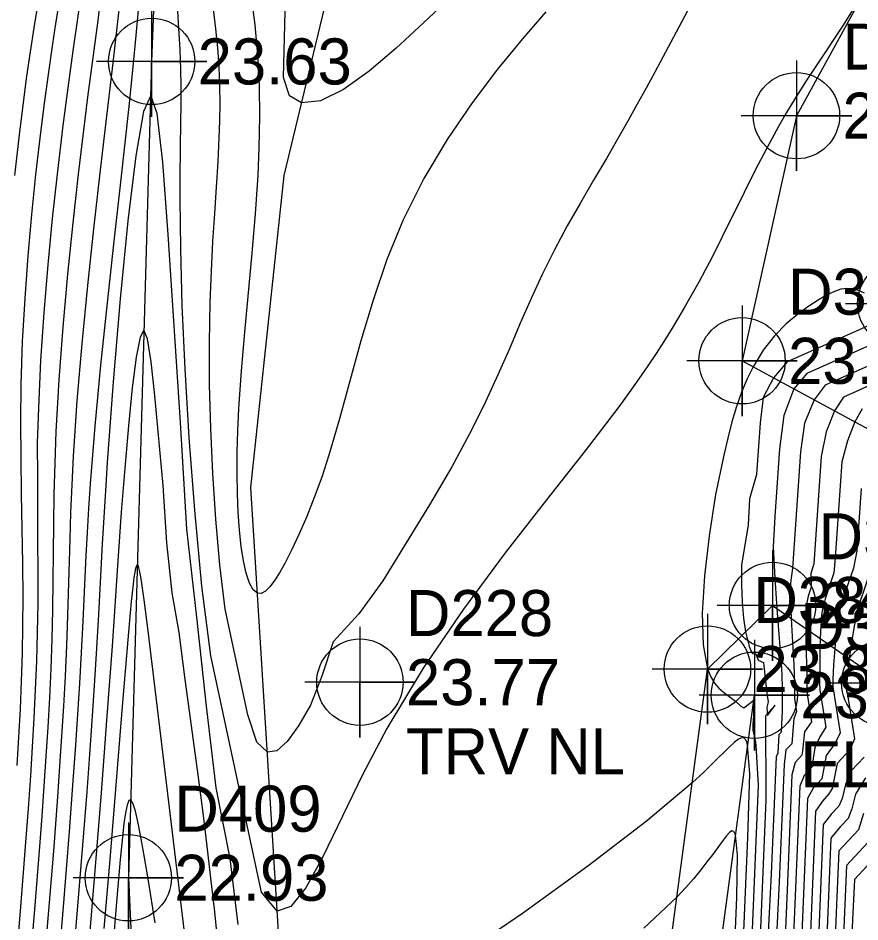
# Model space of a CAD drawing. Extents: x 2356077 to 2359823, y 225951 to 227822.
# Drawn here: x 2356540.32 to 2356586.03, y 227226.48 to 227275.54 of the extents above; entities that cross this region are included whole.
import ezdxf

# ---------------------------------------------------------------- set-up
doc = ezdxf.new("R2010")
doc.units = 0
for name, color, linetype in [('DTM Contours Major', 7, 'Continuous'), ('DTM Contours Minor', 7, 'Continuous'), ('Exist DTM Breakline', 7, 'Continuous'), ('Exist DTM Breakline Cogo Elevation', 7, 'Continuous'), ('Exist DTM Breakline Cogo Number', 7, 'Continuous'), ('Exist DTM Breakline Cogo Point CELL', 7, 'Continuous'), ('Exist DTM Drainline', 7, 'Continuous'), ('Exist DTM Drainline Cogo Comment', 7, 'Continuous'), ('Exist DTM Drainline Cogo Elevation', 7, 'Continuous'), ('Exist DTM Drainline Cogo Number', 7, 'Continuous'), ('Exist DTM Drainline Cogo Point CELL', 7, 'Continuous'), ('Exist DTM Regular Point CELL', 7, 'Continuous'), ('Exist DTM Regular Point Cogo Comment', 7, 'Continuous'), ('Exist DTM Regular Point Cogo Elevation', 7, 'Continuous'), ('Exist DTM Regular Point Cogo Number', 7, 'Continuous'), ('PH Exist DTM Breakline', 7, 'Continuous')]:
    doc.layers.add(name, color=color, linetype=linetype)

msp = doc.modelspace()

# ---------------------------------------------------------------- linework, layer by layer
at = {"layer": 'DTM Contours Major'}
for points in [[(2356545.863, 227276.626), (2356545.708, 227275.192), (2356545.466, 227273.116), (2356545.041, 227269.592), (2356544.734, 227266.981), (2356544.408, 227264.091), (2356544.083, 227261.023), (2356543.779, 227257.879), (2356543.515, 227254.76), (2356543.313, 227251.769), (2356543.232, 227250.207), (2356543.171, 227248.705), (2356543.123, 227247.255), (2356543.004, 227243.122), (2356542.942, 227241.467), (2356542.868, 227239.827), (2356542.781, 227238.196), (2356542.684, 227236.566), (2356542.577, 227234.93), (2356542.46, 227233.279), (2356542.236, 227230.325), (2356541.852, 227225.609)], [(2356576.984, 227276.512), (2356576.192, 227275.047), (2356574.885, 227272.596), (2356574.417, 227271.731), (2356573.94, 227270.86), (2356573.45, 227269.98), (2356572.942, 227269.09), (2356572.263, 227267.925), (2356571.562, 227266.735), (2356570.85, 227265.514), (2356570.141, 227264.256), (2356569.445, 227262.958), (2356568.774, 227261.614), (2356568.176, 227260.316), (2356567.59, 227258.976), (2356566.995, 227257.593), (2356566.372, 227256.171), (2356565.701, 227254.71), (2356564.961, 227253.211), (2356563.864, 227251.188), (2356562.661, 227249.128), (2356561.4, 227247.055), (2356560.128, 227244.994), (2356558.83, 227243.195), (2356557.433, 227241.687), (2356556.839, 227239.877), (2356556.205, 227238.24), (2356555.537, 227237.12), (2356554.927, 227236.272), (2356554.369, 227235.772), (2356553.855, 227235.694), (2356553.279, 227236.237), (2356552.789, 227237.726), (2356551.559, 227243.463), (2356551.275, 227245.855), (2356551.051, 227248.346), (2356550.886, 227250.827), (2356550.777, 227253.27), (2356550.72, 227255.649), (2356550.713, 227257.937), (2356550.752, 227260.107), (2356550.817, 227261.804), (2356550.903, 227263.409), (2356550.998, 227264.926), (2356551.093, 227266.365), (2356551.179, 227267.73), (2356551.244, 227269.03), (2356551.275, 227269.959), (2356551.286, 227270.866), (2356551.273, 227271.885), (2356551.232, 227272.9), (2356551.162, 227273.92), (2356551.062, 227274.956), (2356550.93, 227276.017)], [(2356587.908, 227259.469), (2356582.081, 227256.874), (2356581.332, 227256.017), (2356580.772, 227254.938), (2356580.613, 227253.573), (2356580.418, 227250.761), (2356580.043, 227249.442), (2356579.968, 227248.029), (2356579.601, 227245.844), (2356579.595, 227244.795), (2356579.64, 227243.834), (2356579.716, 227242.974), (2356579.825, 227242.235), (2356579.886, 227241.946), (2356579.953, 227241.681), (2356580.024, 227241.437), (2356580.098, 227241.21), (2356580.206, 227241.054), (2356580.382, 227241.027), (2356580.508, 227240.682), (2356580.788, 227240.568), (2356580.944, 227239.211), (2356580.999, 227238.773), (2356581.054, 227238.425), (2356580.979, 227238.136), (2356581.018, 227237.678), (2356581.433, 227238.239), (2356580.903, 227237.669), (2356580.928, 227233.104), (2356580.177, 227215.223)], [(2356586.099, 227250.001), (2356585.866, 227246.627), (2356585.676, 227245.691), (2356585.056, 227243.861), (2356584.838, 227242.954), (2356584.738, 227242.108), (2356584.663, 227241.324), (2356584.628, 227240.869), (2356584.602, 227240.438), (2356584.567, 227239.63), (2356584.555, 227239.247), (2356584.881, 227237.205), (2356584.956, 227236.739), (2356584.678, 227236.184), (2356584.19, 227235.518), (2356583.963, 227234.24), (2356583.498, 227233.741), (2356583.192, 227233.181), (2356582.829, 227224.549)], [(2356547.761, 227226.437), (2356547.379, 227228.812), (2356547.185, 227229.973), (2356547.005, 227230.989), (2356546.84, 227231.836), (2356546.688, 227232.489), (2356546.551, 227232.923), (2356546.427, 227233.115), (2356546.327, 227233.068), (2356546.236, 227232.826), (2356546.15, 227232.405), (2356546.067, 227231.819), (2356545.984, 227231.084), (2356545.869, 227229.879), (2356545.705, 227227.988), (2356545.434, 227224.703)], [(2356586.466, 227230.801), (2356585.3, 227229.549), (2356585.103, 227224.873)]]:
    msp.add_lwpolyline(points, dxfattribs=at)
at = {"layer": 'DTM Contours Minor'}
for points in [[(2356563.774, 227276.657), (2356562.341, 227275.276), (2356560.853, 227273.898), (2356559.379, 227272.65), (2356557.987, 227271.656), (2356556.744, 227271.045), (2356555.717, 227270.941), (2356555.058, 227271.316), (2356554.728, 227272.312), (2356554.891, 227278.786)], [(2356543.852, 227277.663), (2356543.291, 227273.755), (2356543.014, 227271.748), (2356542.749, 227269.703), (2356542.433, 227267.059), (2356542.174, 227264.669), (2356541.931, 227262.153), (2356541.716, 227259.564), (2356541.544, 227256.956), (2356541.428, 227254.385), (2356541.357, 227252.459), (2356541.365, 227250.684), (2356541.366, 227248.9), (2356541.392, 227243.756), (2356541.312, 227240.643), (2356541.253, 227239.098), (2356541.179, 227237.55), (2356541.09, 227235.992), (2356540.99, 227234.415), (2356540.865, 227232.636), (2356540.729, 227230.819), (2356540.429, 227227.059), (2356539.894, 227220.582)], [(2356544.857, 227277.102), (2356544.642, 227275.415), (2356544.094, 227271.249), (2356543.869, 227269.459), (2356543.583, 227267.062), (2356543.29, 227264.428), (2356543.006, 227261.637), (2356542.748, 227258.767), (2356542.532, 227255.897), (2356542.374, 227253.106), (2356542.31, 227251.374), (2356542.269, 227249.701), (2356542.244, 227248.079), (2356542.194, 227243.44), (2356542.146, 227241.829), (2356542.089, 227240.234), (2356542.017, 227238.647), (2356541.932, 227237.059), (2356541.834, 227235.463), (2356541.726, 227233.85), (2356541.609, 227232.229), (2356541.483, 227230.577), (2356541.208, 227227.152), (2356540.688, 227220.881)], [(2356546.877, 227276.368), (2356546.721, 227274.595), (2356546.556, 227272.898), (2356546.33, 227270.731), (2356545.875, 227266.634), (2356545.516, 227263.429), (2356545.149, 227260.081), (2356544.799, 227256.699), (2356544.486, 227253.391), (2356544.235, 227250.266), (2356544.145, 227248.919), (2356544.069, 227247.625), (2356544.003, 227246.376), (2356543.833, 227242.809), (2356543.746, 227241.111), (2356543.65, 227239.429), (2356543.546, 227237.754), (2356543.435, 227236.08), (2356543.317, 227234.4), (2356543.092, 227231.396), (2356542.763, 227227.301), (2356542.028, 227218.472)], [(2356568.977, 227275.87), (2356567.703, 227274.419), (2356566.349, 227272.768), (2356564.97, 227270.937), (2356563.621, 227268.95), (2356562.357, 227266.827), (2356561.232, 227264.591), (2356560.346, 227262.427), (2356559.592, 227260.225), (2356558.937, 227258.022), (2356557.776, 227253.779), (2356557.199, 227251.819), (2356556.806, 227250.63), (2356556.4, 227249.516), (2356555.99, 227248.483), (2356555.581, 227247.538), (2356555.18, 227246.687), (2356554.795, 227245.938), (2356554.512, 227245.435), (2356554.244, 227245.009), (2356553.989, 227244.672), (2356553.75, 227244.436), (2356553.527, 227244.314), (2356553.32, 227244.318), (2356553.091, 227244.504), (2356552.888, 227244.876), (2356552.711, 227245.408), (2356552.561, 227246.08), (2356552.437, 227246.867), (2356552.341, 227247.747), (2356552.271, 227248.709), (2356552.228, 227249.734), (2356552.21, 227250.817), (2356552.219, 227251.952), (2356552.252, 227253.131), (2356552.308, 227254.348), (2356552.447, 227256.394), (2356552.627, 227258.499), (2356553.029, 227262.783), (2356553.21, 227264.913), (2356553.351, 227267.003), (2356553.399, 227268.004), (2356553.418, 227268.499), (2356553.448, 227270.194), (2356553.423, 227271.865), (2356553.339, 227273.52), (2356553.19, 227275.168), (2356552.972, 227276.817)], [(2356541.383, 227276.323), (2356541.171, 227275.015), (2356540.971, 227273.703), (2356540.782, 227272.379), (2356540.557, 227270.674), (2356540.378, 227269.209), (2356540.133, 227266.994)], [(2356542.481, 227276.017), (2356542.302, 227274.891), (2356542.13, 227273.757), (2356541.963, 227272.604), (2356541.751, 227271.041), (2356541.553, 227269.476), (2356541.271, 227267.041), (2356541.05, 227264.885), (2356540.849, 227262.635), (2356540.679, 227260.321), (2356540.55, 227257.977), (2356540.472, 227255.634), (2356540.449, 227253.637), (2356540.46, 227251.666), (2356540.49, 227249.724), (2356540.56, 227245.934), (2356540.575, 227244.09), (2356540.565, 227242.562), (2356540.536, 227241.05), (2356540.489, 227239.545), (2356540.424, 227238.038), (2356540.345, 227236.518), (2356540.252, 227234.978)], [(2356585.816, 227276.254), (2356585.113, 227275.158), (2356583.759, 227273.109), (2356583.116, 227272.128), (2356582.5, 227271.156), (2356582.048, 227270.408), (2356581.61, 227269.651), (2356580.968, 227268.476), (2356580.347, 227267.277), (2356579.741, 227266.068), (2356578.554, 227263.665), (2356577.962, 227262.496), (2356577.624, 227261.851), (2356577.28, 227261.213), (2356576.927, 227260.576), (2356576.561, 227259.936), (2356576.18, 227259.288), (2356575.778, 227258.626), (2356575.383, 227257.993), (2356574.963, 227257.339), (2356574.514, 227256.661), (2356574.03, 227255.954), (2356573.507, 227255.216), (2356572.941, 227254.441), (2356571.111, 227252.054), (2356569.015, 227249.397), (2356566.773, 227246.514), (2356564.501, 227243.453), (2356562.317, 227240.262), (2356560.34, 227236.986), (2356559.018, 227234.458), (2356556.849, 227229.974), (2356555.949, 227228.337), (2356555.138, 227227.315), (2356554.39, 227227.07), (2356553.539, 227228.096), (2356550.791, 227240.917), (2356550.303, 227244.712), (2356549.912, 227248.826), (2356549.61, 227252.776), (2356549.387, 227256.502), (2356549.237, 227259.942), (2356549.15, 227263.034), (2356549.117, 227265.716), (2356549.118, 227266.766), (2356549.137, 227268.622), (2356549.171, 227270.924), (2356549.173, 227271.858), (2356549.16, 227272.753), (2356549.143, 227273.29), (2356549.12, 227273.834), (2356549.056, 227274.975), (2356548.968, 227276.238)], [(2356552.273, 227226.346), (2356551.833, 227229.926), (2356551.08, 227233.753), (2356550.544, 227238.199), (2356550.026, 227243.023), (2356549.486, 227247.808), (2356549.137, 227253.58), (2356548.476, 227263.793), (2356548.176, 227267.71), (2356547.865, 227270.351), (2356547.519, 227271.339), (2356547.131, 227270.467), (2356546.71, 227268.059), (2356546.279, 227264.532), (2356545.863, 227260.304), (2356545.483, 227255.792), (2356545.165, 227251.414), (2356545.065, 227249.873), (2356544.893, 227247.005), (2356544.678, 227243.161), (2356544.553, 227241.032), (2356544.429, 227239.032), (2356544.304, 227237.134), (2356544.177, 227235.312), (2356544.047, 227233.538), (2356543.823, 227230.648), (2356543.533, 227227.119), (2356542.805, 227218.528)], [(2356586.28, 227260.601), (2356585.954, 227260.755), (2356585.635, 227260.849), (2356585.319, 227260.869), (2356584.993, 227260.819), (2356584.643, 227260.699), (2356584.253, 227260.511), (2356583.809, 227260.257), (2356583.26, 227259.907), (2356582.657, 227259.471), (2356582.026, 227258.935), (2356581.393, 227258.289), (2356580.785, 227257.519), (2356580.226, 227256.615), (2356579.902, 227255.952), (2356579.605, 227255.23), (2356579.334, 227254.453), (2356579.083, 227253.624), (2356578.851, 227252.745), (2356578.632, 227251.821), (2356578.196, 227249.673), (2356577.838, 227247.445), (2356577.587, 227245.26), (2356577.47, 227243.244), (2356577.515, 227241.52), (2356577.752, 227240.211), (2356577.927, 227239.785), (2356578.136, 227239.448), (2356578.371, 227239.178), (2356578.622, 227238.957), (2356579.134, 227238.572), (2356579.28, 227238.455), (2356579.565, 227238.201), (2356579.734, 227238.101), (2356580.264, 227238.514), (2356580.249, 227238.219), (2356580.245, 227237.821), (2356580.247, 227237.661), (2356580.239, 227237.454), (2356580.223, 227237.185), (2356580.216, 227236.885), (2356580.289, 227236.58), (2356580.354, 227236.245), (2356580.383, 227236.065), (2356580.51, 227233.908), (2356579.704, 227214.729)], [(2356551.154, 227225.581), (2356550.981, 227227.187), (2356550.793, 227228.859), (2356550.587, 227230.6), (2356550.361, 227232.411), (2356550.058, 227234.731), (2356549.399, 227239.64), (2356549.067, 227242.198), (2356548.691, 227244.337), (2356548.397, 227247.056), (2356548.193, 227250.165), (2356547.747, 227255.045), (2356547.549, 227256.887), (2356547.354, 227258.123), (2356547.155, 227258.599), (2356546.949, 227258.227), (2356546.735, 227257.132), (2356546.519, 227255.475), (2356546.308, 227253.416), (2356546.107, 227251.114), (2356545.922, 227248.73), (2356545.736, 227246.085), (2356545.419, 227241.442), (2356545.128, 227237.406), (2356544.828, 227233.49), (2356544.504, 227229.482), (2356544.135, 227225.107)], [(2356588.484, 227258.635), (2356583.142, 227256.256), (2356582.437, 227255.419), (2356581.894, 227253.967), (2356581.662, 227252.165), (2356581.408, 227248.484), (2356581.319, 227246.848), (2356581.403, 227245.139), (2356581.499, 227243.758), (2356581.519, 227243.502), (2356581.705, 227241.173), (2356581.752, 227240.5), (2356581.787, 227239.851), (2356581.808, 227239.21), (2356581.812, 227238.574), (2356581.801, 227237.914), (2356581.772, 227237.213), (2356581.75, 227236.807), (2356581.798, 227236.817), (2356581.634, 227236.641), (2356581.573, 227235.65), (2356581.478, 227235.438), (2356581.211, 227229.087), (2356581.047, 227225.915)], [(2356588.947, 227257.751), (2356584.137, 227255.608), (2356583.543, 227254.82), (2356583.028, 227253.561), (2356582.797, 227251.989), (2356582.361, 227245.69), (2356582.307, 227245.29), (2356582.268, 227244.863), (2356582.254, 227244.401), (2356582.266, 227243.904), (2356582.305, 227242.957), (2356582.376, 227241.641), (2356582.441, 227240.457), (2356582.463, 227239.89), (2356582.476, 227239.329), (2356582.476, 227238.617), (2356582.589, 227237.911), (2356582.447, 227237.498), (2356582.398, 227237.083), (2356582.325, 227236.157), (2356582.01, 227235.82), (2356581.913, 227235.033), (2356581.646, 227228.666), (2356581.346, 227222.377)], [(2356589.385, 227256.856), (2356585.138, 227254.964), (2356584.648, 227254.222), (2356584.191, 227253.089), (2356583.927, 227251.748), (2356583.524, 227245.913), (2356583.362, 227245.394), (2356583.382, 227244.65), (2356583.216, 227244.159), (2356583.104, 227243.613), (2356583.093, 227242.996), (2356583.091, 227242.413), (2356583.096, 227241.823), (2356583.144, 227239.728), (2356583.148, 227239.235), (2356583.165, 227238.848), (2356583.407, 227237.337), (2356583.022, 227236.802), (2356582.968, 227236.295), (2356582.904, 227235.757), (2356582.882, 227235.53), (2356582.506, 227235.127), (2356582.342, 227234.471), (2356582.079, 227228.209), (2356581.949, 227225.25)], [(2356586.155, 227254.327), (2356585.754, 227253.624), (2356585.349, 227252.601), (2356585.053, 227251.458), (2356584.693, 227246.246), (2356584.614, 227245.421), (2356584.138, 227244.015), (2356583.962, 227243.287), (2356583.912, 227242.554), (2356583.877, 227241.868), (2356583.859, 227241.349), (2356583.846, 227240.389), (2356583.842, 227239.499), (2356583.855, 227239.071), (2356584.18, 227237.047), (2356583.85, 227236.521), (2356583.579, 227235.923), (2356583.494, 227235.344), (2356583.434, 227234.898), (2356583.003, 227234.435), (2356582.767, 227233.846), (2356582.392, 227224.908)], [(2356549.615, 227223.829), (2356549.006, 227228.786), (2356547.377, 227242.284), (2356547.164, 227243.972), (2356547.042, 227244.85), (2356546.987, 227245.204), (2356546.934, 227245.488), (2356546.885, 227245.695), (2356546.837, 227245.821), (2356546.791, 227245.859), (2356546.746, 227245.807), (2356546.702, 227245.672), (2356546.657, 227245.458), (2356546.612, 227245.172), (2356546.567, 227244.819), (2356546.464, 227243.869), (2356546.406, 227243.265), (2356546.273, 227241.795), (2356545.971, 227238.181), (2356545.295, 227229.862), (2356544.983, 227226.121)], [(2356586.725, 227245.926), (2356585.963, 227243.675), (2356585.729, 227242.626), (2356585.572, 227241.664), (2356585.449, 227240.78), (2356585.403, 227240.391), (2356585.332, 227239.667), (2356585.304, 227239.326), (2356585.295, 227239.022), (2356585.347, 227238.822), (2356585.733, 227236.423), (2356585.475, 227235.814), (2356584.799, 227235.082), (2356584.519, 227233.724), (2356584.35, 227233.431), (2356583.99, 227233.044), (2356583.614, 227232.485), (2356583.266, 227224.176)], [(2356579.28, 227215.387), (2356579.938, 227231.057), (2356580.061, 227234.526), (2356579.931, 227236.075), (2356579.882, 227236.254), (2356579.822, 227236.379), (2356579.751, 227236.453), (2356579.665, 227236.479), (2356579.564, 227236.461), (2356579.444, 227236.4), (2356579.205, 227236.219), (2356578.905, 227235.941), (2356578.086, 227235.13), (2356577.549, 227234.61), (2356576.917, 227234.025), (2356574.42, 227231.931), (2356571.253, 227229.505), (2356567.705, 227226.948), (2356564.062, 227224.463)], [(2356586.261, 227235.433), (2356585.571, 227234.692), (2356585.24, 227233.932), (2356585.065, 227233.188), (2356584.879, 227232.773), (2356584.479, 227232.344), (2356584.036, 227231.768), (2356583.702, 227223.811)], [(2356586.341, 227234.294), (2356585.796, 227233.422), (2356585.59, 227232.628), (2356585.39, 227232.097), (2356584.96, 227231.635), (2356584.457, 227231.023), (2356584.138, 227223.423)], [(2356586.224, 227232.375), (2356585.957, 227231.48), (2356584.888, 227230.333), (2356584.776, 227227.851), (2356584.576, 227223.075)], [(2356578.816, 227215.111), (2356579.35, 227227.833), (2356579.391, 227230.125), (2356579.275, 227231.21), (2356579.192, 227231.388), (2356579.081, 227231.427), (2356578.94, 227231.341), (2356578.761, 227231.145), (2356578.542, 227230.855), (2356578.019, 227230.131), (2356577.724, 227229.736), (2356577.386, 227229.305), (2356577.003, 227228.842), (2356576.57, 227228.349), (2356576.084, 227227.831), (2356574.29, 227226.142)], [(2356587.079, 227230.234), (2356585.737, 227228.793), (2356585.628, 227226.598), (2356585.446, 227222.275)]]:
    msp.add_lwpolyline(points, dxfattribs=at)
at = {"layer": 'Exist DTM Breakline'}
for points in [[(2356592.549, 227288.356), (2356582.582, 227270.24), (2356579.63, 227256.937), (2356592.641, 227249.897), (2356595.601, 227262.555), (2356603.607, 227269.245)], [(2356575.82, 227148.639), (2356572.681, 227182.58), (2356573.963, 227212.061), (2356577.748, 227240.207), (2356581.287, 227243.662), (2356587.377, 227239.444), (2356592.648, 227232.822), (2356591.439, 227218.21), (2356593.678, 227194.877), (2356594.225, 227153.117)]]:
    msp.add_lwpolyline(points, dxfattribs=at)
at = {"layer": 'Exist DTM Breakline Cogo Point CELL'}
for points in [[(2356582.582, 227273.24), (2356582.582, 227267.24), (2356582.582, 227270.24), (2356585.582, 227270.24), (2356579.582, 227270.24)], [(2356579.63, 227259.937), (2356579.63, 227253.937), (2356579.63, 227256.937), (2356582.63, 227256.937), (2356576.63, 227256.937)], [(2356581.287, 227246.662), (2356581.287, 227240.662), (2356581.287, 227243.662), (2356584.287, 227243.662), (2356578.287, 227243.662)], [(2356577.748, 227243.207), (2356577.748, 227237.207), (2356577.748, 227240.207), (2356580.748, 227240.207), (2356574.748, 227240.207)], [(2356587.377, 227242.444), (2356587.377, 227236.444), (2356587.377, 227239.444), (2356590.377, 227239.444), (2356584.377, 227239.444)]]:
    msp.add_lwpolyline(points, dxfattribs=at)
for centre in [(2356582.582, 227270.24), (2356579.63, 227256.937), (2356581.287, 227243.662), (2356577.748, 227240.207), (2356587.377, 227239.444)]:
    msp.add_circle(centre, 2.344, dxfattribs=at)
at = {"layer": 'Exist DTM Drainline'}
for points in [[(2356548.776, 227304.309), (2356547.572, 227273.186), (2356546.306, 227228.878), (2356548.057, 227191.22), (2356550.765, 227150.688), (2356554.732, 227113.271), (2356560.954, 227074.926), (2356573.805, 227008.735)], [(2356578.049, 227148.523), (2356575.562, 227182.67), (2356576.732, 227212.358), (2356580.297, 227238.787)]]:
    msp.add_lwpolyline(points, dxfattribs=at)
at = {"layer": 'Exist DTM Drainline Cogo Point CELL'}
for points in [[(2356547.572, 227276.186), (2356547.572, 227270.186), (2356547.572, 227273.186), (2356550.572, 227273.186), (2356544.572, 227273.186)], [(2356588.247, 227263.035), (2356588.247, 227257.035), (2356588.247, 227260.035), (2356591.247, 227260.035), (2356585.247, 227260.035)], [(2356580.297, 227241.787), (2356580.297, 227235.787), (2356580.297, 227238.787), (2356583.297, 227238.787), (2356577.297, 227238.787)], [(2356546.306, 227231.878), (2356546.306, 227225.878), (2356546.306, 227228.878), (2356549.306, 227228.878), (2356543.306, 227228.878)]]:
    msp.add_lwpolyline(points, dxfattribs=at)
for centre in [(2356547.572, 227273.186), (2356588.247, 227260.035), (2356580.297, 227238.787), (2356546.306, 227228.878)]:
    msp.add_circle(centre, 2.344, dxfattribs=at)
at = {"layer": 'Exist DTM Regular Point CELL'}
msp.add_lwpolyline([(2356558.882, 227242.494), (2356558.882, 227236.494), (2356558.882, 227239.494), (2356561.882, 227239.494), (2356555.882, 227239.494)], dxfattribs=at)
msp.add_circle((2356558.882, 227239.494), 2.344, dxfattribs=at)
at = {"layer": 'PH Exist DTM Breakline'}
msp.add_lwpolyline([(2356554.802, 227220.421), (2356552.964, 227250.065), (2356554.762, 227266.989), (2356558.085, 227280.739), (2356558.431, 227290.839), (2356559.137, 227302.225), (2356558.722, 227311.603), (2356557.308, 227318.008), (2356555.736, 227323.861), (2356552.945, 227329.698)], dxfattribs=at)

# ---------------------------------------------------------------- texts
at = {"layer": 'Exist DTM Breakline Cogo Elevation'}
for s, p in [('23.77', (2356585.082, 227268.99)), ('23.69', (2356582.13, 227255.687)), ('24.14', (2356583.787, 227242.412)), ('23.80', (2356580.248, 227238.957))]:
    msp.add_text(s, height=2.5, dxfattribs=at).set_placement(p)
at = {"layer": 'Exist DTM Breakline Cogo Number'}
for s, p in [('D373', (2356585.082, 227272.74)), ('D374', (2356582.13, 227259.437)), ('D391', (2356583.787, 227246.162)), ('D389', (2356580.248, 227242.707))]:
    msp.add_text(s, height=2.5, dxfattribs=at).set_placement(p)
at = {"layer": 'Exist DTM Drainline Cogo Comment'}
msp.add_text('EL*4003', height=2.5, dxfattribs=at).set_placement((2356582.797, 227233.787))
at = {"layer": 'Exist DTM Drainline Cogo Elevation'}
for s, p in [('23.63', (2356550.072, 227271.936)), ('23.71', (2356582.797, 227237.537)), ('22.93', (2356548.806, 227227.628))]:
    msp.add_text(s, height=2.5, dxfattribs=at).set_placement(p)
at = {"layer": 'Exist DTM Drainline Cogo Number'}
for s, p in [('D390', (2356582.797, 227241.287)), ('D409', (2356548.806, 227231.378))]:
    msp.add_text(s, height=2.5, dxfattribs=at).set_placement(p)
at = {"layer": 'Exist DTM Regular Point Cogo Comment'}
msp.add_text('TRV NL', height=2.5, dxfattribs=at).set_placement((2356561.382, 227234.495))
at = {"layer": 'Exist DTM Regular Point Cogo Elevation'}
msp.add_text('23.77', height=2.5, dxfattribs=at).set_placement((2356561.382, 227238.245))
at = {"layer": 'Exist DTM Regular Point Cogo Number'}
msp.add_text('D228', height=2.5, dxfattribs=at).set_placement((2356561.382, 227241.995))

doc.saveas('drawing.dxf')
